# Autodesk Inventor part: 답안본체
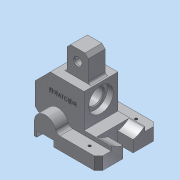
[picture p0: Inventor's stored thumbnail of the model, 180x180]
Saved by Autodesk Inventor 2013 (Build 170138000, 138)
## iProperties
Created: 2016-11
Part Number: 답안본체
Material: 알루미늄 6061
Document SubType Name: Modeling
Designer: Administrator
Density: 2.71 g/cm^3
Mass: 472.773 g
Surface Area: 322.301 cm^2
Volume: 174.455 cm^3
Author: Administrator
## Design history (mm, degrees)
sketch "스케치2"
  geometry: L1 (-38, 35)-(38, 35); L2 (38, 35)-(38, -35); L3 (38, -35)-(-38, -35); L4 (-38, -35)-(-38, 35); L5 (-38, 35)-(38, -35); L6 (38, 35)-(-38, -35); 1 further point
  constraints: 12 end point, 2 midpoint, 2 parallel, 1 horizontal, 1 perpendicular
  dimensions: "d0" = 76 distance of L2.end L3.end; "d1" = 70 distance of L1.end L2.end
extrude "돌출1" new body sketch "스케치2" distance "d2" = 15; taper "d3" = 0 deg
sketch "스케치5"
  geometry: C1 r 13 at (13, 15); 2 further points
  constraints: 1 centre point, 1 horizontal alignment
  dimensions: "d11" = 26 diameter of C1; "d13" = 13 distance of C1.centre point (0, 15)
extrude "돌출3" join sketch "스케치5" stored distance "d14" = 15; taper "d15" = 0 deg
sketch "스케치3"
  geometry: L1 (3, 7)-(23, 7); L2 (23, 7)-(23, 0); L3 (23, 0)-(3, 0); L4 (3, 0)-(3, 7); L5 (0, 0)-(0, 15) reference; 1 further point
  constraints: 8 end point, 2 parallel, 1 horizontal, 1 horizontal alignment, 1 perpendicular
  dimensions: "d4" = 20 distance of L2.end L3.end; "d5" = 7 distance of L1.end L2.end; "d6" = 3 distance between parallel lines of L4 L5
extrude "돌출2" cut sketch "스케치3" stored distance "d7" = 15; taper "d8" = 0 deg
fillet "모깎기1" dims "d16" = 5
sketch "스케치6"
  geometry: L1 (-38, 15)-(7.708, 15) reference; L2 (-38, 0)-(-38, 15) reference; L3 (35, 7)-(15, 7) reference; L4 (15, 7)-(15, 0) reference; L5 (15, 0)-(-38, 0) reference; L6 (-38, 0)-(-38, 15) reference; L7 (-38, 15)-(7.708, 15) reference; L8 (38, 15)-(38, 0) reference; L9 (38, 0)-(35, 0) reference; L10 (35, 0)-(35, 7) reference; L11 (34, 60)-(-6, 60); L12 (-6, 60)-(-6, 20); L13 (-6, 20)-(-38, 20); L14 (52, 42)-(52, 16); L15 (48, 12)-(-38, 12); L16 (-38, 12)-(-38, 20); L17 (34, 60)-(52, 42); L18 (52, 16)-(48, 12); A1 r 5 centre (7.708, 20) between (7.708, 15) and (12.512, 18.611) reference; A2 r 13 centre (25, 15) between (38, 15) and (12.512, 18.611) reference; 3 further points
  constraints: 16 end point, 5 point on line, 4 perpendicular
  dimensions: "d85" = 60 distance between parallel lines of L5 L11; "d89" = 58 distance of point (52, 60) L11.end; "d90" = 48 distance of point (52, 60) point (52, 12); "d91" = 18 distance of L11.start point (52, 60); "d92" = 18 distance of L14.start point (52, 60) (= d91); "d93" = 4 distance of L14.end point (52, 12); "d94" = 4 distance of L15.start point (52, 12) (= d93); "d95" = 48 distance between parallel lines of L15 L11
extrude "돌출4" join sketch "스케치6" stored distance "d26" = 40; taper "d27" = 0 deg
hole "구멍1" diameter "d30" = 20; stored, may be unused: countersink angle "d34" = 90 deg, drill point angle "d36" = 118 deg; dims "d28" = 42, "d29" = 20, "d31" = 6, "d32" = 29, "d33" = 7, "d35" = 8
chamfer "모따기1" distance "d37" = 1; stored, may be unused: second distance "d38" = 2, angle "d39" = 45 deg
sketch "스케치7"
  geometry: L1 (2, 52)-(1, 53) reference; L2 (1, 53)-(1, 56.5) reference; L3 (1, 56.5)-(-6, 56.5) reference; L4 (-6, 56.5)-(-6, 60) reference; L5 (-6, 60)-(34, 60) reference; L6 (42, 52)-(2, 52) reference; L7 (35, 7)-(15, 7) reference; L8 (15, 7)-(15, 0) reference; L9 (15, 0)-(-38, 0) reference; L10 (-38, 0)-(-38, 20) reference; L11 (-38, 20)-(-6, 20) reference; L12 (-6, 20)-(-6, 27.5) reference; L13 (-6, 27.5)-(1, 27.5) reference; L14 (1, 27.5)-(1, 31) reference; L15 (1, 31)-(2, 32) reference; L16 (2, 32)-(52, 32) reference; L17 (38, 12)-(38, 0) reference; L18 (38, 0)-(35, 0) reference; L19 (35, 0)-(35, 7) reference; L20 (-1, 60)-(-1, 86); L21 (3, 90)-(20, 90); L22 (24, 86)-(24, 60); L23 (20, 90)-(24, 86); L24 (3, 90)-(-1, 86); L25 (34, 60)-(42, 52) reference; L26 (52, 32)-(52, 16) reference; L27 (52, 16)-(48, 12) reference; L28 (48, 12)-(38, 12) reference; 3 further points
  constraints: 10 end point, 6 point on line, 2 perpendicular, 1 parallel
  dimensions: "d40" = 5 distance between parallel lines of L4 L20; "d41" = 25 distance between parallel lines of L20 L22; "d42" = 90 distance between parallel lines of L9 L21; "d43" = 4 distance of L21.end point (24, 90); "d44" = 4 distance of L22.start point (24, 90) (= d43); "d45" = 4 distance of L21.start point (-1, 90) (= d43); "d46" = 4 distance of L20.end point (-1, 90) (= d45)
extrude "돌출5" join sketch "스케치7" stored distance "d47" = 20; taper "d48" = 0 deg
fillet "모깎기2" dims "d49" = 3
hole "구멍2" diameter "d52" = 8; stored, may be unused: countersink angle "d56" = 90 deg, drill point angle "d58" = 118 deg; dims "d50" = 77, "d51" = 12.5, "d53" = 6, "d54" = 29, "d55" = 7, "d57" = 8
chamfer "모따기2" distance "d59" = 1; stored, may be unused: second distance "d60" = 2, angle "d61" = 45 deg
chamfer "모따기3" distance "d62" = 5; stored, may be unused: second distance "d63" = 2, angle "d64" = 45 deg
hole "구멍3" diameter "d67" = 3.242; stored, may be unused: countersink angle "d71" = 90 deg, drill point angle "d73" = 118 deg; dims "d65" = 18, "d66" = 7.5, "d68" = 18, "d69" = 29, "d70" = 7, "d72" = 8
node "작업 평면1"
sketch "스케치9"
  geometry: L1 (20, 50)-(20, -10) reference; L2 (20, 14)-(5, 14); L3 (5, 14)-(5, 26); L4 (5, 26)-(20, 26); L5 (20, 26)-(20, 14); C1 r 29 at (-22, 20); 3 further points
  constraints: 8 end point, 3 midpoint, 2 parallel, 1 centre point, 1 horizontal, 1 horizontal alignment, 1 perpendicular
  dimensions: "d79" = 58 diameter of C1; "d80" = 42 distance of point (20, 20) C1.centre; "d81" = 15 distance of L3.end L4.end; "d82" = 12 distance of L2.end L3.end
extrude "돌출6" cut sketch "스케치9" distance "d83" = 18; taper "d84" = 0 deg
sketch "스케치8"
  geometry: L1 (6, 20)-(6, 60) reference; 4 further points; 1 other entity
  constraints: 2 other
  dimensions: "d75" = 18 dimension on point (-19, 42); "d76" = 25 distance from line of point (-19, 42) L1
feature "엠보싱1" sketch "스케치8" dims "d77" = 0.5, "d78" = 0
node "솔리드1"
mirror "대칭1"
node "절단 모서리 투영1"
node "절단 모서리 투영2"
